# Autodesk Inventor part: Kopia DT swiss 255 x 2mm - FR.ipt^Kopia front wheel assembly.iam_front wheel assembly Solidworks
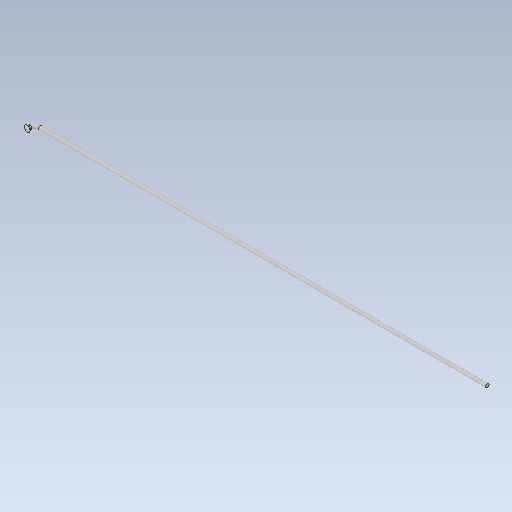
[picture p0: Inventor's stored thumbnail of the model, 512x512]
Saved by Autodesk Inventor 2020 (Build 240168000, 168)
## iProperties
Created: 2017-09
Part Number: Kopia DT swiss 255 x 2mm - FR.ipt^Kopia front wheel assembly.iam_front wheel assembly Solidworks
Material: Ogólny
Document SubType Name: Modeling
Designer: Tomasz
Density: 1 g/cm^3
Appearance: Domyślna
Sending System: SolidWorks 2017
Last Author: Tomasz
Last Saved: 2017-09-11
Author: Tomasz
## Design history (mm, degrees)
feature "DT swiss 255 x 2mm - FR.ipt"
node "Bryła1"
